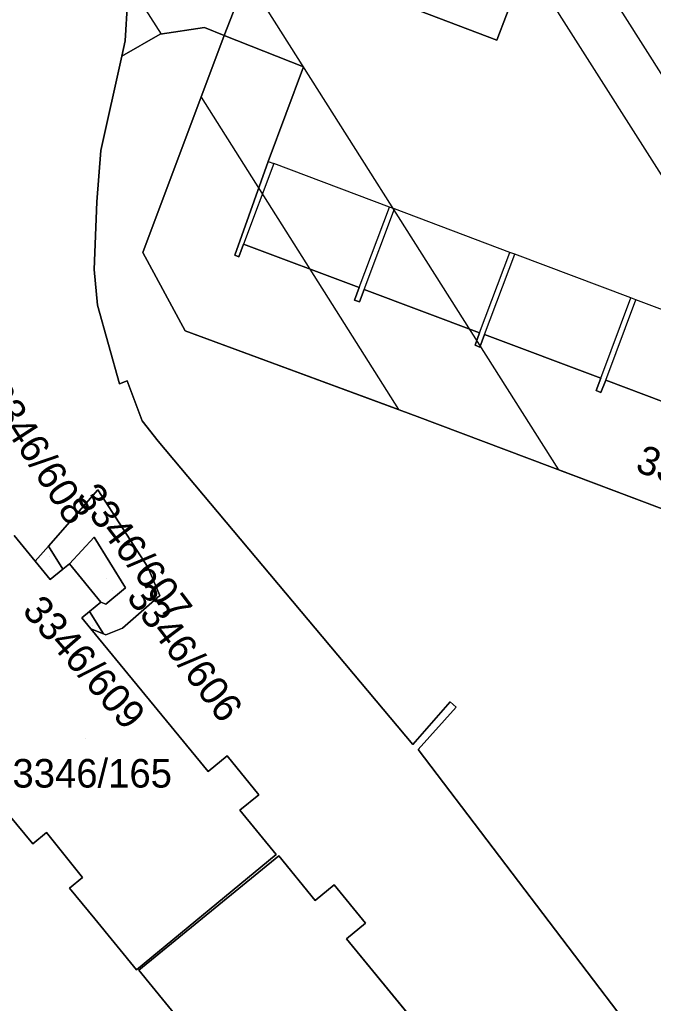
# Model space of a CAD drawing. Extents: x -262715 to -259381, y -1237238 to -1231182.
# Drawn here: x -262116.2 to -262071.9, y -1235529.3 to -1235460.5 of the extents above; entities that cross this region are included whole.
import ezdxf

# ---------------------------------------------------------------- set-up
doc = ezdxf.new("R2010")
doc.units = 0
for name, color, linetype in [('body_kn', 7, 'Continuous'), ('kladpar_druhypozemkov', 7, 'Continuous'), ('kladpar_hranice', 7, 'Continuous'), ('kladpar_parcelnecisla', 7, 'Continuous'), ('kladpar_plochy', 7, 'Continuous'), ('kladpar_sipky', 7, 'Continuous'), ('tarchy_linie', 7, 'Continuous'), ('zappar_hrandruhpozemk', 7, 'Continuous')]:
    doc.layers.add(name, color=color, linetype=linetype)

msp = doc.modelspace()

# ---------------------------------------------------------------- linework, layer by layer
at = {"layer": 'body_kn'}
for p, q in [((-262103.27, -1235461.06), (-262103.27, -1235461.06)), ((-262108.83, -1235461.99), (-262108.83, -1235461.99)), ((-262106.38, -1235461.54), (-262106.38, -1235461.54)), ((-262106.32, -1235461.53), (-262106.32, -1235461.53)), ((-262106.32, -1235461.53), (-262106.32, -1235461.53)), ((-262101.9, -1235461.63), (-262101.9, -1235461.63)), ((-262082.84, -1235461.95), (-262082.84, -1235461.95)), ((-262109.07, -1235463.07), (-262109.07, -1235463.07)), ((-262096.35, -1235463.82), (-262096.35, -1235463.82)), ((-262096.35, -1235463.82), (-262096.35, -1235463.82)), ((-262103.52, -1235465.95), (-262103.52, -1235465.95)), ((-262103.52, -1235465.95), (-262103.52, -1235465.95)), ((-262110.52, -1235469.67), (-262110.52, -1235469.67)), ((-262098.82, -1235470.45), (-262098.82, -1235470.45)), ((-262098.82, -1235470.45), (-262098.82, -1235470.45)), ((-262098.44, -1235470.59), (-262098.44, -1235470.59)), ((-262098.44, -1235470.59), (-262098.44, -1235470.59)), ((-262110.81, -1235473.27), (-262110.81, -1235473.27)), ((-262090.34, -1235473.63), (-262090.34, -1235473.63)), ((-262090.34, -1235473.63), (-262090.34, -1235473.63)), ((-262090, -1235473.76), (-262090, -1235473.76)), ((-262090, -1235473.76), (-262090, -1235473.76)), ((-262100.55, -1235476.22), (-262100.55, -1235476.22)), ((-262107.6, -1235476.8), (-262107.6, -1235476.8)), ((-262101.17, -1235476.99), (-262101.17, -1235476.99)), ((-262100.88, -1235477.1), (-262100.88, -1235477.1)), ((-262081.92, -1235476.8), (-262081.92, -1235476.8)), ((-262081.92, -1235476.8), (-262081.92, -1235476.8)), ((-262081.58, -1235476.93), (-262081.58, -1235476.93)), ((-262081.58, -1235476.93), (-262081.58, -1235476.93)), ((-262111, -1235478), (-262111, -1235478)), ((-262092.46, -1235479.26), (-262092.46, -1235479.26)), ((-262092.46, -1235479.26), (-262092.46, -1235479.26)), ((-262092.11, -1235479.39), (-262092.11, -1235479.39)), ((-262092.11, -1235479.39), (-262092.11, -1235479.39)), ((-262110.76, -1235480.48), (-262110.76, -1235480.48)), ((-262092.78, -1235480.13), (-262092.78, -1235480.13)), ((-262092.44, -1235480.26), (-262092.44, -1235480.26)), ((-262073.46, -1235479.98), (-262073.46, -1235479.98)), ((-262073.46, -1235479.98), (-262073.46, -1235479.98)), ((-262073.11, -1235480.11), (-262073.11, -1235480.11)), ((-262073.11, -1235480.11), (-262073.11, -1235480.11)), ((-262104.64, -1235482.28), (-262104.64, -1235482.28)), ((-262084.04, -1235482.42), (-262084.04, -1235482.42)), ((-262084.04, -1235482.42), (-262084.04, -1235482.42)), ((-262083.69, -1235482.55), (-262083.69, -1235482.55)), ((-262083.69, -1235482.55), (-262083.69, -1235482.55)), ((-262084.36, -1235483.29), (-262084.36, -1235483.29)), ((-262084.02, -1235483.42), (-262084.02, -1235483.42)), ((-262109.23, -1235486), (-262109.23, -1235486)), ((-262108.7, -1235485.77), (-262108.7, -1235485.77)), ((-262075.57, -1235485.6), (-262075.57, -1235485.6)), ((-262075.57, -1235485.6), (-262075.57, -1235485.6)), ((-262075.22, -1235485.74), (-262075.22, -1235485.74)), ((-262075.22, -1235485.74), (-262075.22, -1235485.74)), ((-262075.89, -1235486.46), (-262075.89, -1235486.46)), ((-262075.55, -1235486.59), (-262075.55, -1235486.59)), ((-262089.72, -1235487.79), (-262089.72, -1235487.79)), ((-262107.63, -1235488.58), (-262107.63, -1235488.58)), ((-262088.41, -1235488.28), (-262088.41, -1235488.28)), ((-262106.51, -1235489.99), (-262106.51, -1235489.99)), ((-262078.51, -1235492.01), (-262078.51, -1235492.01)), ((-262110.73, -1235493.4), (-262110.73, -1235493.4)), ((-262110.99, -1235496.72), (-262110.99, -1235496.72)), ((-262114.19, -1235497.35), (-262114.19, -1235497.35)), ((-262115.12, -1235498.4), (-262115.12, -1235498.4)), ((-262115.12, -1235498.4), (-262115.12, -1235498.4)), ((-262113.18, -1235498.95), (-262113.18, -1235498.95)), ((-262112.73, -1235498.58), (-262112.73, -1235498.58)), ((-262107.24, -1235498.82), (-262107.24, -1235498.82)), ((-262114.07, -1235499.68), (-262114.07, -1235499.68)), ((-262108.81, -1235500.25), (-262108.81, -1235500.25)), ((-262106.41, -1235500.8), (-262106.41, -1235500.8)), ((-262111.32, -1235501.91), (-262111.32, -1235501.91)), ((-262110.52, -1235501.27), (-262110.52, -1235501.27)), ((-262110.52, -1235501.27), (-262110.52, -1235501.27)), ((-262110.17, -1235501.39), (-262110.17, -1235501.39)), ((-262110.17, -1235501.39), (-262110.17, -1235501.39)), ((-262111.87, -1235502.35), (-262111.87, -1235502.35)), ((-262111.23, -1235503.13), (-262111.23, -1235503.13)), ((-262109.02, -1235503.09), (-262109.02, -1235503.09)), ((-262110.35, -1235503.47), (-262110.35, -1235503.47)), ((-262110.35, -1235503.47), (-262110.35, -1235503.47)), ((-262110.17, -1235503.54), (-262110.17, -1235503.54)), ((-262086.09, -1235508.23), (-262086.09, -1235508.23)), ((-262085.67, -1235508.61), (-262085.67, -1235508.61)), ((-262088.7, -1235511.21), (-262088.7, -1235511.21)), ((-262088.33, -1235511.57), (-262088.33, -1235511.57)), ((-262101.7, -1235512.01), (-262101.7, -1235512.01)), ((-262103.03, -1235513.11), (-262103.03, -1235513.11)), ((-262099.49, -1235514.73), (-262099.49, -1235514.73)), ((-262100.82, -1235515.8), (-262100.82, -1235515.8)), ((-262114.34, -1235517.38), (-262114.34, -1235517.38)), ((-262115.29, -1235518.17), (-262115.29, -1235518.17)), ((-262098.26, -1235518.92), (-262098.26, -1235518.92)), ((-262098.09, -1235519.01), (-262098.09, -1235519.01)), ((-262098.09, -1235519.01), (-262098.09, -1235519.01)), ((-262111.82, -1235520.51), (-262111.82, -1235520.51)), ((-262094.2, -1235521.03), (-262094.2, -1235521.03)), ((-262112.72, -1235521.26), (-262112.72, -1235521.26)), ((-262095.54, -1235522.13), (-262095.54, -1235522.13)), ((-262110.96, -1235523.41), (-262110.96, -1235523.41)), ((-262092.01, -1235523.71), (-262092.01, -1235523.71)), ((-262093.34, -1235524.8), (-262093.34, -1235524.8)), ((-262108.03, -1235526.98), (-262108.03, -1235526.98)), ((-262108.03, -1235526.98), (-262108.03, -1235526.98)), ((-262107.88, -1235527), (-262107.88, -1235527))]:
    msp.add_line(p, q, dxfattribs=at)
at = {"layer": 'kladpar_druhypozemkov'}
for p, q in [((-262111.1, -1235495.82), (-262111.1, -1235495.82)), ((-262113.75, -1235499.06), (-262113.75, -1235499.06)), ((-262110.15, -1235499.61), (-262110.15, -1235499.61)), ((-262110.75, -1235502.85), (-262110.75, -1235502.85)), ((-262111.58, -1235510.8), (-262111.58, -1235510.8))]:
    msp.add_line(p, q, dxfattribs=at)
at = {"layer": 'kladpar_hranice'}
for points in [[(-262080.81, -1235456.62), (-262082.84, -1235461.95), (-262099.55, -1235455.59), (-262101.9, -1235461.63), (-262103.27, -1235461.06), (-262106.38, -1235461.54), (-262109.07, -1235463.07), (-262108.83, -1235461.99), (-262108.67, -1235459.3)], [(-262067.06, -1235488.8), (-262075.22, -1235485.74), (-262075.55, -1235486.59), (-262075.89, -1235486.46), (-262075.57, -1235485.6), (-262083.69, -1235482.55), (-262084.02, -1235483.42), (-262084.36, -1235483.29), (-262084.04, -1235482.42), (-262092.11, -1235479.39), (-262092.44, -1235480.26), (-262092.78, -1235480.13), (-262092.46, -1235479.26), (-262100.55, -1235476.22), (-262100.88, -1235477.1), (-262101.17, -1235476.99), (-262098.82, -1235470.45), (-262096.35, -1235463.82), (-262101.9, -1235461.63), (-262099.55, -1235455.59), (-262082.84, -1235461.95), (-262080.81, -1235456.62)], [(-262108.67, -1235459.3), (-262108.83, -1235461.99), (-262109.07, -1235463.07), (-262110.52, -1235469.67), (-262110.81, -1235473.27), (-262111, -1235478), (-262110.76, -1235480.48), (-262109.23, -1235486), (-262108.7, -1235485.77), (-262107.63, -1235488.58), (-262106.51, -1235489.99), (-262088.7, -1235511.21), (-262086.09, -1235508.23), (-262085.67, -1235508.61), (-262088.33, -1235511.57), (-262072.6, -1235532.26)], [(-262072.6, -1235532.26), (-262088.33, -1235511.57), (-262085.67, -1235508.61), (-262086.09, -1235508.23), (-262088.7, -1235511.21), (-262106.51, -1235489.99), (-262107.63, -1235488.58), (-262108.7, -1235485.77), (-262109.23, -1235486), (-262110.76, -1235480.48), (-262111, -1235478), (-262110.81, -1235473.27), (-262110.52, -1235469.67), (-262109.07, -1235463.07), (-262106.38, -1235461.54), (-262103.27, -1235461.06), (-262101.9, -1235461.63), (-262107.6, -1235476.8), (-262104.64, -1235482.28), (-262088.41, -1235488.28), (-262069.85, -1235495.28), (-262049.19, -1235503.04), (-262028.18, -1235510.93)], [(-262028.18, -1235510.93), (-262049.19, -1235503.04), (-262069.85, -1235495.28), (-262088.41, -1235488.28), (-262104.64, -1235482.28), (-262107.6, -1235476.8), (-262101.9, -1235461.63), (-262096.35, -1235463.82)], [(-262096.35, -1235463.82), (-262098.82, -1235470.45), (-262101.17, -1235476.99), (-262100.88, -1235477.1), (-262100.55, -1235476.22), (-262092.46, -1235479.26), (-262092.78, -1235480.13), (-262092.44, -1235480.26), (-262092.11, -1235479.39), (-262084.04, -1235482.42), (-262084.36, -1235483.29), (-262084.02, -1235483.42), (-262083.69, -1235482.55), (-262075.57, -1235485.6), (-262075.89, -1235486.46), (-262075.55, -1235486.59), (-262075.22, -1235485.74), (-262067.06, -1235488.8)], [(-262119.23, -1235513.42), (-262115.29, -1235518.17), (-262114.34, -1235517.38), (-262111.82, -1235520.51), (-262112.72, -1235521.26), (-262110.96, -1235523.41), (-262108.03, -1235526.98), (-262098.26, -1235518.92), (-262100.82, -1235515.8), (-262099.49, -1235514.73), (-262101.7, -1235512.01), (-262103.03, -1235513.11), (-262111.23, -1235503.13), (-262110.35, -1235503.47), (-262110.17, -1235503.54), (-262109.02, -1235503.09), (-262106.41, -1235500.8), (-262107.24, -1235498.82), (-262110.73, -1235493.4), (-262114.19, -1235497.35), (-262115.12, -1235498.4), (-262116.59, -1235496.61)], [(-262110.52, -1235501.27), (-262110.17, -1235501.39), (-262108.81, -1235500.25), (-262110.99, -1235496.72), (-262112.73, -1235498.58), (-262113.18, -1235498.95), (-262114.19, -1235497.35), (-262110.73, -1235493.4), (-262107.24, -1235498.82), (-262106.41, -1235500.8), (-262109.02, -1235503.09), (-262110.17, -1235503.54), (-262110.35, -1235503.47), (-262111.32, -1235501.91), (-262110.52, -1235501.27)], [(-262116.59, -1235496.61), (-262115.12, -1235498.4), (-262114.07, -1235499.68), (-262113.18, -1235498.95), (-262112.73, -1235498.58), (-262110.52, -1235501.27), (-262111.32, -1235501.91), (-262111.87, -1235502.35), (-262111.23, -1235503.13), (-262103.03, -1235513.11), (-262101.7, -1235512.01), (-262099.49, -1235514.73), (-262100.82, -1235515.8), (-262098.26, -1235518.92), (-262108.03, -1235526.98)], [(-262110.17, -1235501.39), (-262110.52, -1235501.27), (-262112.73, -1235498.58), (-262110.99, -1235496.72), (-262108.81, -1235500.25), (-262110.17, -1235501.39)], [(-262115.12, -1235498.4), (-262114.19, -1235497.35), (-262113.18, -1235498.95), (-262114.07, -1235499.68), (-262115.12, -1235498.4)], [(-262110.35, -1235503.47), (-262111.23, -1235503.13), (-262111.87, -1235502.35), (-262111.32, -1235501.91), (-262110.35, -1235503.47)], [(-262108.03, -1235526.98), (-262110.96, -1235523.41), (-262112.72, -1235521.26), (-262111.82, -1235520.51), (-262114.34, -1235517.38), (-262115.29, -1235518.17), (-262119.23, -1235513.42)], [(-262098.09, -1235519.01), (-262095.54, -1235522.13), (-262094.2, -1235521.03), (-262092.01, -1235523.71), (-262093.34, -1235524.8), (-262084.55, -1235535.52), (-262083.22, -1235534.43), (-262080.99, -1235537.15), (-262082.32, -1235538.24), (-262079.77, -1235541.35), (-262089.5, -1235549.42), (-262094.18, -1235543.71), (-262093.26, -1235542.97), (-262095.84, -1235539.82), (-262096.75, -1235540.57), (-262100.63, -1235535.84), (-262099.72, -1235535.1), (-262102.28, -1235531.96), (-262103.2, -1235532.71), (-262107.88, -1235527), (-262098.09, -1235519.01)], [(-262084.55, -1235535.52), (-262093.34, -1235524.8), (-262092.01, -1235523.71), (-262094.2, -1235521.03), (-262095.54, -1235522.13), (-262098.09, -1235519.01), (-262107.88, -1235527), (-262103.2, -1235532.71)]]:
    msp.add_lwpolyline(points, dxfattribs=at)
at = {"layer": 'kladpar_plochy'}
for p, q in [((-262108.67, -1235459.3), (-262108.83, -1235461.99)), ((-262108.83, -1235461.99), (-262109.07, -1235463.07)), ((-262109.07, -1235463.07), (-262110.52, -1235469.67)), ((-262110.52, -1235469.67), (-262110.81, -1235473.27)), ((-262110.81, -1235473.27), (-262111, -1235478)), ((-262111, -1235478), (-262110.76, -1235480.48)), ((-262110.76, -1235480.48), (-262109.23, -1235486)), ((-262109.23, -1235486), (-262108.7, -1235485.77)), ((-262108.7, -1235485.77), (-262107.63, -1235488.58)), ((-262107.63, -1235488.58), (-262106.51, -1235489.99)), ((-262106.51, -1235489.99), (-262088.7, -1235511.21)), ((-262110.73, -1235493.4), (-262114.19, -1235497.35)), ((-262107.24, -1235498.82), (-262110.73, -1235493.4)), ((-262115.12, -1235498.4), (-262116.59, -1235496.61)), ((-262114.19, -1235497.35), (-262115.12, -1235498.4)), ((-262106.41, -1235500.8), (-262107.24, -1235498.82)), ((-262109.02, -1235503.09), (-262106.41, -1235500.8)), ((-262103.03, -1235513.11), (-262111.23, -1235503.13)), ((-262111.23, -1235503.13), (-262110.35, -1235503.47)), ((-262110.17, -1235503.54), (-262109.02, -1235503.09)), ((-262110.35, -1235503.47), (-262110.17, -1235503.54)), ((-262088.7, -1235511.21), (-262086.09, -1235508.23)), ((-262085.67, -1235508.61), (-262088.33, -1235511.57)), ((-262086.09, -1235508.23), (-262085.67, -1235508.61)), ((-262088.33, -1235511.57), (-262072.6, -1235532.26)), ((-262101.7, -1235512.01), (-262103.03, -1235513.11)), ((-262099.49, -1235514.73), (-262101.7, -1235512.01)), ((-262119.23, -1235513.42), (-262115.29, -1235518.17)), ((-262100.82, -1235515.8), (-262099.49, -1235514.73)), ((-262098.26, -1235518.92), (-262100.82, -1235515.8)), ((-262115.29, -1235518.17), (-262114.34, -1235517.38)), ((-262114.34, -1235517.38), (-262111.82, -1235520.51)), ((-262108.03, -1235526.98), (-262098.26, -1235518.92)), ((-262098.09, -1235519.01), (-262107.88, -1235527)), ((-262095.54, -1235522.13), (-262098.09, -1235519.01)), ((-262111.82, -1235520.51), (-262112.72, -1235521.26)), ((-262094.2, -1235521.03), (-262095.54, -1235522.13)), ((-262092.01, -1235523.71), (-262094.2, -1235521.03)), ((-262112.72, -1235521.26), (-262110.96, -1235523.41)), ((-262110.96, -1235523.41), (-262108.03, -1235526.98)), ((-262093.34, -1235524.8), (-262092.01, -1235523.71)), ((-262084.55, -1235535.52), (-262093.34, -1235524.8)), ((-262107.88, -1235527), (-262103.2, -1235532.71))]:
    msp.add_line(p, q, dxfattribs=at)
for points in [[(-262080.81, -1235456.62), (-262082.84, -1235461.95), (-262099.55, -1235455.59), (-262101.9, -1235461.63), (-262103.27, -1235461.06), (-262106.38, -1235461.54), (-262109.07, -1235463.07), (-262108.83, -1235461.99), (-262108.67, -1235459.3)], [(-262067.06, -1235488.8), (-262075.22, -1235485.74), (-262075.55, -1235486.59), (-262075.89, -1235486.46), (-262075.57, -1235485.6), (-262083.69, -1235482.55), (-262084.02, -1235483.42), (-262084.36, -1235483.29), (-262084.04, -1235482.42), (-262092.11, -1235479.39), (-262092.44, -1235480.26), (-262092.78, -1235480.13), (-262092.46, -1235479.26), (-262100.55, -1235476.22), (-262100.88, -1235477.1), (-262101.17, -1235476.99), (-262098.82, -1235470.45), (-262096.35, -1235463.82), (-262101.9, -1235461.63), (-262099.55, -1235455.59), (-262082.84, -1235461.95), (-262080.81, -1235456.62)], [(-262072.6, -1235532.26), (-262088.33, -1235511.57), (-262085.67, -1235508.61), (-262086.09, -1235508.23), (-262088.7, -1235511.21), (-262106.51, -1235489.99), (-262107.63, -1235488.58), (-262108.7, -1235485.77), (-262109.23, -1235486), (-262110.76, -1235480.48), (-262111, -1235478), (-262110.81, -1235473.27), (-262110.52, -1235469.67), (-262109.07, -1235463.07), (-262106.38, -1235461.54), (-262103.27, -1235461.06), (-262101.9, -1235461.63), (-262107.6, -1235476.8), (-262104.64, -1235482.28), (-262088.41, -1235488.28), (-262069.85, -1235495.28), (-262049.19, -1235503.04), (-262028.18, -1235510.93)], [(-262069.85, -1235495.28), (-262088.41, -1235488.28), (-262104.64, -1235482.28), (-262107.6, -1235476.8), (-262101.9, -1235461.63), (-262096.35, -1235463.82), (-262098.82, -1235470.45), (-262101.17, -1235476.99), (-262100.88, -1235477.1), (-262100.55, -1235476.22), (-262092.46, -1235479.26), (-262092.78, -1235480.13), (-262092.44, -1235480.26), (-262092.11, -1235479.39), (-262084.04, -1235482.42), (-262084.36, -1235483.29), (-262084.02, -1235483.42), (-262083.69, -1235482.55), (-262075.57, -1235485.6), (-262075.89, -1235486.46), (-262075.55, -1235486.59), (-262075.22, -1235485.74), (-262067.06, -1235488.8)], [(-262116.59, -1235496.61), (-262115.12, -1235498.4), (-262114.07, -1235499.68), (-262113.18, -1235498.95), (-262112.73, -1235498.58), (-262110.52, -1235501.27), (-262111.32, -1235501.91), (-262111.87, -1235502.35), (-262111.23, -1235503.13), (-262103.03, -1235513.11), (-262101.7, -1235512.01), (-262099.49, -1235514.73), (-262100.82, -1235515.8), (-262098.26, -1235518.92), (-262108.03, -1235526.98), (-262110.96, -1235523.41), (-262112.72, -1235521.26), (-262111.82, -1235520.51), (-262114.34, -1235517.38), (-262115.29, -1235518.17), (-262119.23, -1235513.42)]]:
    msp.add_lwpolyline(points, dxfattribs=at)
for points in [[(-262110.52, -1235501.27), (-262110.17, -1235501.39), (-262108.81, -1235500.25), (-262110.99, -1235496.72), (-262112.73, -1235498.58), (-262113.18, -1235498.95), (-262114.19, -1235497.35), (-262110.73, -1235493.4), (-262107.24, -1235498.82), (-262106.41, -1235500.8), (-262109.02, -1235503.09), (-262110.17, -1235503.54), (-262110.35, -1235503.47), (-262111.32, -1235501.91)], [(-262110.17, -1235501.39), (-262110.52, -1235501.27), (-262112.73, -1235498.58), (-262110.99, -1235496.72), (-262108.81, -1235500.25)], [(-262115.12, -1235498.4), (-262114.19, -1235497.35), (-262113.18, -1235498.95), (-262114.07, -1235499.68)], [(-262110.35, -1235503.47), (-262111.23, -1235503.13), (-262111.87, -1235502.35), (-262111.32, -1235501.91)], [(-262098.09, -1235519.01), (-262095.54, -1235522.13), (-262094.2, -1235521.03), (-262092.01, -1235523.71), (-262093.34, -1235524.8), (-262084.55, -1235535.52), (-262083.22, -1235534.43), (-262080.99, -1235537.15), (-262082.32, -1235538.24), (-262079.77, -1235541.35), (-262089.5, -1235549.42), (-262094.18, -1235543.71), (-262093.26, -1235542.97), (-262095.84, -1235539.82), (-262096.75, -1235540.57), (-262100.63, -1235535.84), (-262099.72, -1235535.1), (-262102.28, -1235531.96), (-262103.2, -1235532.71), (-262107.88, -1235527)]]:
    msp.add_lwpolyline(points, close=True, dxfattribs=at)
at = {"layer": 'kladpar_sipky'}
for p, q in [((-262114.12, -1235498.09), (-262114.12, -1235498.09)), ((-262109.69, -1235500.44), (-262109.69, -1235500.44)), ((-262111.12, -1235502.89), (-262111.12, -1235502.89))]:
    msp.add_line(p, q, dxfattribs=at)
at = {"layer": 'tarchy_linie'}
for points in [[(-262079.16, -1235435.34), (-262076.34, -1235436.48), (-262073.46, -1235428.74), (-262037.21, -1235442.33), (-262012.14, -1235482.41), (-262013.46, -1235481.92), (-262017.16, -1235480.54), (-262018.19, -1235483.44), (-262019.58, -1235487.22), (-262022.07, -1235493.48), (-262025.28, -1235502.71), (-262028.18, -1235510.93), (-262045.96, -1235504.25), (-262092.46, -1235431.02), (-262086.55, -1235433.21), (-262081.62, -1235419.93), (-262076.17, -1235421.94), (-262077.63, -1235422.83), (-262080.31, -1235430.07), (-262080.52, -1235433.02), (-262079.16, -1235435.34)], [(-262103.46, -1235452.59), (-262102.77, -1235451.03), (-262087.09, -1235457.15), (-262084.58, -1235450.53), (-262051.82, -1235502.05), (-262069.85, -1235495.28), (-262078.51, -1235492.01), (-262103.46, -1235452.59)], [(-262106.32, -1235461.53), (-262106.38, -1235461.54), (-262109.07, -1235463.07), (-262108.83, -1235461.99), (-262108.67, -1235459.3), (-262109.24, -1235456.91), (-262106.32, -1235461.53)], [(-262103.52, -1235465.95), (-262089.72, -1235487.79), (-262104.64, -1235482.28), (-262107.6, -1235476.8), (-262103.52, -1235465.95)]]:
    msp.add_lwpolyline(points, dxfattribs=at)
at = {"layer": 'zappar_hrandruhpozemk'}
for p, q in [((-262098.44, -1235470.59), (-262100.55, -1235476.22)), ((-262098.82, -1235470.45), (-262098.44, -1235470.59)), ((-262090.34, -1235473.63), (-262098.44, -1235470.59)), ((-262092.46, -1235479.26), (-262090.34, -1235473.63)), ((-262090, -1235473.76), (-262090.34, -1235473.63)), ((-262092.11, -1235479.39), (-262090, -1235473.76)), ((-262081.92, -1235476.8), (-262090, -1235473.76)), ((-262084.04, -1235482.42), (-262081.92, -1235476.8)), ((-262083.69, -1235482.55), (-262081.58, -1235476.93)), ((-262081.58, -1235476.93), (-262081.92, -1235476.8)), ((-262073.46, -1235479.98), (-262081.58, -1235476.93)), ((-262075.57, -1235485.6), (-262073.46, -1235479.98)), ((-262075.22, -1235485.74), (-262073.11, -1235480.11)), ((-262073.11, -1235480.11), (-262073.46, -1235479.98)), ((-262064.94, -1235483.18), (-262073.11, -1235480.11))]:
    msp.add_line(p, q, dxfattribs=at)

# ---------------------------------------------------------------- texts
at = {"layer": 'kladpar_parcelnecisla'}
for s, rotation, p in [('3346/608', 303, (-262118.855, -1235486.659)), ('3346/148', 340, (-262073.233, -1235492.078)), ('3346/607', 307, (-262112.327, -1235493.922)), ('3346/606', 307, (-262108.796, -1235500.915)), ('3346/609', 311, (-262116.096, -1235501.903))]:
    msp.add_text(s, height=2, rotation=rotation, dxfattribs=at).set_placement(p)
msp.add_text('3346/165', height=2, dxfattribs=at).set_placement((-262116.712, -1235514.23))

doc.saveas('drawing.dxf')
